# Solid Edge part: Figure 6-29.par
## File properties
Author: TIET
Template: Iso Metric Part.par
Last saved by: CADCIM
Revision: 6
Application: Solid Edge
Accuracy: 0.990
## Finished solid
Body 1: solid body, 4 faces, 3 edges, 0 vertices.
  Faces by surface: plane 2, cone 1, spun 1
  Edges by curve: circle 3
Bounding box of the edges (mm; curved faces can reach further): 80.923 x 80.923 x 108.443, from (-40.4615, -40.4615, -39.4389) to (40.4615, 40.4615, 69.0045).
Conical faces (half-angle, radius in mm at the cone's reference point): 45.1754 deg R15.0535 x1
Planar faces by outward normal: +z 1, -z 1
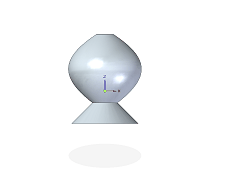
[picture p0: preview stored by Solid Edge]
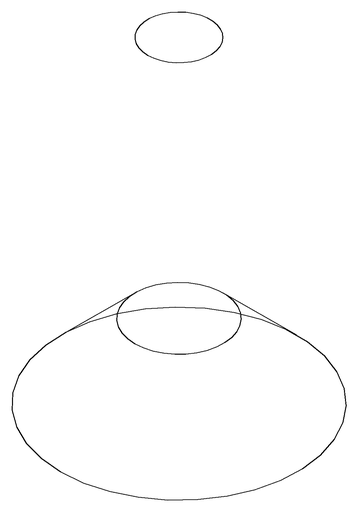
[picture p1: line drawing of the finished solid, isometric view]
